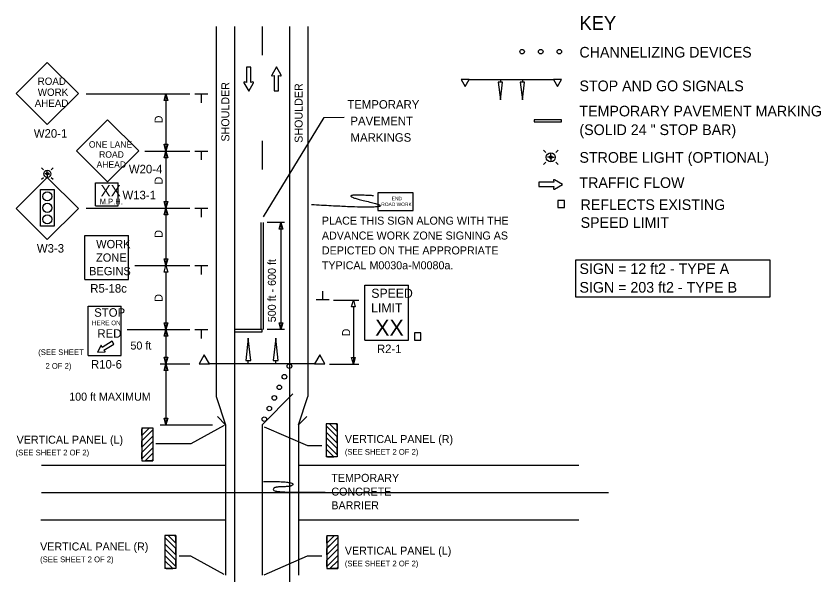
# Model space of a CAD drawing. Extents: x 16739 to 18486, y 7218 to 8208.
# Drawn here: x 16739 to 17443, y 7706 to 8195 of the extents above; entities that cross this region are included whole.
import ezdxf

# ---------------------------------------------------------------- set-up
doc = ezdxf.new("R2010")
doc.units = 0
for name, color, linetype in [('ALI_LEGAL_EX', 7, 'Continuous'), ('MT_SCRATCH_LEVEL_E', 7, 'Continuous'), ('PAVT_EDGE_EX', 7, 'Continuous'), ('TRAFFIC_SIGNS_PR', 7, 'Continuous'), ('TYPICAL_TEXT_DIMEN_EX', 7, 'Continuous'), ('TYPICAL_TEXT_DIMEN_PR', 7, 'Continuous')]:
    doc.layers.add(name, color=color, linetype=linetype)

msp = doc.modelspace()

# ---------------------------------------------------------------- linework, layer by layer
at = {"layer": 'ALI_LEGAL_EX'}
for points in [[(16953.78, 8185.68), (16953.78, 8160.68)], [(16953.78, 8085.68), (16953.78, 8060.68)], [(16952.78, 8014.45), (16952.78, 7920.82)], [(16954.78, 8014.45), (16954.78, 7920.82)]]:
    msp.add_lwpolyline(points, dxfattribs=at)
at = {"layer": 'MT_SCRATCH_LEVEL_E'}
for p, q in [((16943.98, 8150.09), (16940.24, 8150.09)), ((16940.24, 8150.09), (16940.24, 8136.83)), ((16943.98, 8150.09), (16940.24, 8150.09)), ((16940.24, 8150.09), (16940.24, 8136.83)), ((16943.98, 8136.83), (16943.98, 8150.09)), ((16943.98, 8136.83), (16943.98, 8150.09)), ((16966.37, 8150.35), (16962.26, 8143.11)), ((16966.37, 8150.35), (16962.26, 8143.11)), ((16970.52, 8143.11), (16966.37, 8150.35)), ((16970.52, 8143.11), (16966.37, 8150.35)), ((16962.74, 8142.43), (16964.52, 8142.74)), ((16962.74, 8142.43), (16964.52, 8142.74)), ((16964.52, 8142.74), (16964.52, 8129.49)), ((16964.52, 8142.74), (16964.52, 8129.49)), ((16968.26, 8129.49), (16968.26, 8142.74)), ((16968.26, 8142.74), (16970.04, 8142.43)), ((16968.26, 8129.49), (16968.26, 8142.74)), ((16968.26, 8142.74), (16970.04, 8142.43)), ((16937.98, 8136.47), (16942.13, 8129.22)), ((16937.98, 8136.47), (16942.13, 8129.22)), ((16940.24, 8136.83), (16938.46, 8137.15)), ((16940.24, 8136.83), (16938.46, 8137.15)), ((16942.13, 8129.22), (16946.24, 8136.47)), ((16942.13, 8129.22), (16946.24, 8136.47)), ((16945.76, 8137.15), (16943.98, 8136.83)), ((16945.76, 8137.15), (16943.98, 8136.83)), ((16964.52, 8129.49), (16968.26, 8129.49)), ((16964.52, 8129.49), (16968.26, 8129.49)), ((17209.15, 8049.47), (17195.89, 8049.47)), ((17195.89, 8049.47), (17195.89, 8045.73)), ((17209.15, 8049.47), (17195.89, 8049.47)), ((17195.89, 8049.47), (17195.89, 8045.73)), ((17208.83, 8051.25), (17209.15, 8049.47)), ((17208.83, 8051.25), (17209.15, 8049.47)), ((17216.75, 8047.62), (17209.51, 8051.73)), ((17216.75, 8047.62), (17209.51, 8051.73)), ((17209.51, 8043.48), (17216.75, 8047.62)), ((17209.51, 8043.48), (17216.75, 8047.62)), ((17195.89, 8045.73), (17209.15, 8045.73)), ((17195.89, 8045.73), (17209.15, 8045.73)), ((17209.15, 8045.73), (17208.83, 8043.95)), ((17209.15, 8045.73), (17208.83, 8043.95))]:
    msp.add_line(p, q, dxfattribs=at)
for centre, start, end in [((16962.67, 8142.89), 150.42484, 279.96381), ((16962.67, 8142.89), 150.42484, 279.96381), ((16970.11, 8142.89), 260.03619, 29.77312), ((16970.11, 8142.89), 260.03619, 29.77312), ((16938.39, 8136.69), 80.03619, 209.77312), ((16938.39, 8136.69), 80.03619, 209.77312), ((16945.83, 8136.69), 330.42484, 99.96381), ((16945.83, 8136.69), 330.42484, 99.96381), ((17209.29, 8051.33), 60.42484, 189.96381), ((17209.29, 8051.33), 60.42484, 189.96381), ((17209.29, 8043.88), 170.03619, 299.77312), ((17209.29, 8043.88), 170.03619, 299.77312)]:
    msp.add_arc(centre, 0.463, start, end, dxfattribs=at)
at = {"layer": 'PAVT_EDGE_EX'}
for p, q in [((16913.78, 8185.68), (16913.78, 7862.31)), ((16929.78, 8185.68), (16929.78, 7363.75)), ((16977.78, 8185.68), (16977.78, 7363.75)), ((16993.78, 8185.68), (16993.78, 7862.31)), ((16953.78, 7837.6), (16980.8, 7864.62)), ((16913.78, 7862.31), (16921.78, 7837.6)), ((16985.78, 7837.6), (16993.78, 7862.31)), ((16921.78, 7837.6), (16914.71, 7844.68)), ((16985.78, 7837.6), (16992.85, 7844.68)), ((16921.78, 7837.6), (16921.78, 7706.21)), ((16953.78, 7837.6), (16953.78, 7706.21)), ((16985.78, 7837.6), (16985.78, 7706.21)), ((16760.93, 7802.34), (16921.78, 7802.34)), ((16985.78, 7802.34), (17230.97, 7802.34)), ((16760.93, 7778.34), (17256.97, 7778.34)), ((16760.41, 7754.34), (16921.78, 7754.34)), ((16985.78, 7754.34), (17230.97, 7754.34))]:
    msp.add_line(p, q, dxfattribs=at)
for points in [[(16760.93, 7778.34), (16785.93, 7778.34)], [(16860.93, 7778.34), (16885.93, 7778.34)], [(17060.93, 7778.34), (17085.93, 7778.34)], [(17160.93, 7778.34), (17185.93, 7778.34)]]:
    msp.add_lwpolyline(points, dxfattribs=at)
at = {"layer": 'TRAFFIC_SIGNS_PR'}
for p, q in [((16766, 8154.21), (16738.85, 8127.05)), ((16793.15, 8127.05), (16766, 8154.21)), ((17135.1, 8139.38), (17208.7, 8139.38)), ((17162.3, 8139.38), (17162.3, 8136.97)), ((17181.5, 8139.38), (17181.5, 8136.97)), ((16738.85, 8127.05), (16766, 8099.9)), ((16766, 8099.9), (16793.15, 8127.05)), ((16818.78, 8104.04), (16791.63, 8076.89)), ((16845.93, 8076.89), (16818.78, 8104.04)), ((16791.63, 8076.89), (16818.78, 8049.73)), ((16818.78, 8049.73), (16845.93, 8076.89)), ((17202.13, 8075.61), (17200.09, 8077.65)), ((17210.69, 8075.61), (17212.72, 8077.65)), ((17206.41, 8071.33), (17203.53, 8071.33)), ((17206.41, 8071.33), (17206.41, 8074.21)), ((17206.41, 8071.33), (17206.41, 8067.4)), ((17206.41, 8071.33), (17209.28, 8071.33)), ((16762.58, 8060.35), (16760.95, 8061.98)), ((16769.43, 8060.35), (16771.05, 8061.98)), ((17202.13, 8067.05), (17200.09, 8065.02)), ((17212.72, 8065.02), (17210.69, 8067.05)), ((16766, 8053.77), (16738.85, 8026.62)), ((16762.58, 8053.5), (16760.95, 8051.87)), ((16766, 8056.92), (16763.7, 8056.92)), ((16766, 8056.92), (16766, 8059.23)), ((16766, 8056.92), (16766, 8053.77)), ((16766, 8056.92), (16768.3, 8056.92)), ((16793.15, 8026.62), (16766, 8053.77)), ((16771.05, 8051.87), (16769.43, 8053.5)), ((16808.18, 8048.88), (16828.03, 8048.88)), ((16808.18, 8029.03), (16808.18, 8048.88)), ((16828.03, 8029.03), (16828.03, 8048.88)), ((16738.85, 8026.62), (16766, 7999.47)), ((16766, 7999.47), (16793.15, 8026.62)), ((16808.18, 8029.03), (16828.03, 8029.03)), ((16798.72, 7964.51), (16798.72, 8002.91)), ((16798.72, 8002.91), (16837.12, 8002.91)), ((16837.12, 7964.51), (16837.12, 8002.91)), ((16798.72, 7964.51), (16837.12, 7964.51)), ((17043.66, 7959.64), (17082.06, 7959.64)), ((17043.66, 7911.64), (17043.66, 7959.64)), ((17082.06, 7911.64), (17082.06, 7959.64)), ((16801.79, 7941.3), (16830.59, 7941.3)), ((16801.79, 7898.1), (16801.79, 7941.3)), ((16816.19, 7941.3), (16816.19, 7941.3)), ((16830.59, 7898.1), (16830.59, 7941.3)), ((17043.66, 7911.64), (17082.06, 7911.64)), ((16801.79, 7898.1), (16830.59, 7898.1)), ((16941.78, 7890.82), (16941.78, 7893.84)), ((16965.78, 7890.82), (16965.78, 7893.84)), ((16999.78, 7890.82), (16907.78, 7890.82)), ((17019.53, 7838.39), (17009.93, 7838.39)), ((17009.93, 7838.39), (17009.93, 7809.59)), ((17019.53, 7827.12), (17009.93, 7836.72)), ((17019.53, 7831.64), (17012.78, 7838.39)), ((17019.53, 7837.3), (17018.44, 7838.39)), ((17019.53, 7838.39), (17019.53, 7809.59)), ((16848.65, 7834.79), (16858.25, 7834.79)), ((16848.65, 7834.79), (16848.65, 7805.99)), ((16848.65, 7833.71), (16849.74, 7834.79)), ((16848.65, 7828.05), (16855.4, 7834.79)), ((16848.65, 7823.52), (16858.25, 7833.12)), ((16858.25, 7834.79), (16858.25, 7805.99)), ((17019.53, 7821.46), (17009.93, 7831.06)), ((16848.65, 7817.87), (16858.25, 7827.47)), ((16848.65, 7813.34), (16858.25, 7822.94)), ((16850.07, 7824.94), (16851.48, 7826.35)), ((17019.53, 7816.93), (17009.93, 7826.53)), ((16848.65, 7807.68), (16858.25, 7817.28)), ((17019.53, 7811.28), (17009.93, 7820.88)), ((17016.7, 7809.59), (17009.93, 7816.35)), ((16851.49, 7805.99), (16858.25, 7812.76)), ((16857.15, 7805.99), (16858.25, 7807.1)), ((17011.04, 7809.59), (17009.93, 7810.69)), ((17019.53, 7809.59), (17009.93, 7809.59)), ((16848.65, 7805.99), (16858.25, 7805.99)), ((16878.5, 7740.81), (16868.9, 7740.81)), ((16868.9, 7740.81), (16868.9, 7712.01)), ((16878.5, 7729.54), (16868.9, 7739.14)), ((16878.5, 7734.06), (16871.76, 7740.81)), ((16878.5, 7739.72), (16877.41, 7740.81)), ((16878.5, 7740.81), (16878.5, 7712.01)), ((17010.4, 7740.81), (17020, 7740.81)), ((17010.4, 7740.81), (17010.4, 7712.01)), ((17010.4, 7739.72), (17011.49, 7740.81)), ((17010.4, 7734.06), (17017.15, 7740.81)), ((17010.4, 7729.54), (17020, 7739.14)), ((17020, 7740.81), (17020, 7712.01)), ((16878.5, 7723.88), (16868.9, 7733.48)), ((17010.4, 7723.88), (17020, 7733.48)), ((17011.81, 7730.95), (17013.23, 7732.36)), ((16878.5, 7719.35), (16868.9, 7728.95)), ((16878.5, 7713.7), (16868.9, 7723.3)), ((17010.4, 7719.35), (17020, 7728.95)), ((17010.4, 7713.7), (17020, 7723.3)), ((16875.67, 7712.01), (16868.9, 7718.77)), ((17013.24, 7712.01), (17020, 7718.77)), ((16870.01, 7712.01), (16868.9, 7713.11)), ((16878.5, 7712.01), (16868.9, 7712.01)), ((17010.4, 7712.01), (17020, 7712.01)), ((17018.89, 7712.01), (17020, 7713.11))]:
    msp.add_line(p, q, dxfattribs=at)
for points in [[(17127.9, 8139.38), (17131.5, 8133.15), (17135.1, 8139.38)], [(17208.7, 8139.38), (17212.3, 8133.15), (17215.9, 8139.38)], [(17160.5, 8136.97), (17162.3, 8121.43), (17164.1, 8136.97)], [(17179.7, 8136.97), (17181.5, 8121.43), (17183.3, 8136.97)], [(17191.9, 8104.19), (17191.9, 8102.19), (17215.9, 8102.19), (17215.9, 8104.19)], [(16772.06, 8011.17), (16760.06, 8011.17), (16760.06, 8043.17), (16772.06, 8043.17)], [(17055.24, 8024.86), (17085.96, 8024.86), (17085.96, 8040.22), (17055.24, 8040.22)], [(17212.65, 8027.42), (17218.24, 8027.42), (17218.24, 8033.6), (17212.65, 8033.6)], [(16929.78, 7920.82), (16929.78, 7918.82), (16953.78, 7918.82), (16953.78, 7920.82)], [(16944.03, 7893.84), (16941.78, 7913.26), (16939.53, 7893.84)], [(16968.03, 7893.84), (16965.78, 7913.26), (16963.53, 7893.84)], [(17087.07, 7911.64), (17092.67, 7911.64), (17092.67, 7917.81), (17087.07, 7917.81)], [(16907.78, 7890.82), (16903.28, 7898.62), (16898.78, 7890.82)], [(17008.78, 7890.82), (17004.28, 7898.62), (16999.78, 7890.82)], [(17019.53, 7827.12), (17009.93, 7836.72), (17009.93, 7831.06), (17019.53, 7821.46)], [(17018.44, 7838.39), (17012.78, 7838.39), (17019.53, 7831.64), (17019.53, 7837.3)], [(16849.74, 7834.79), (16855.4, 7834.79), (16848.65, 7828.05), (16848.65, 7833.71)], [(16848.65, 7823.52), (16858.25, 7833.12), (16858.25, 7827.47), (16848.65, 7817.87)], [(16848.65, 7813.34), (16858.25, 7822.94), (16858.25, 7817.28), (16848.65, 7807.68)], [(17019.53, 7816.93), (17009.93, 7826.53), (17009.93, 7820.88), (17019.53, 7811.28)], [(17009.93, 7816.35), (17009.93, 7810.69), (17011.04, 7809.59), (17016.7, 7809.59)], [(16858.25, 7812.76), (16858.25, 7807.1), (16857.15, 7805.99), (16851.49, 7805.99)], [(16878.5, 7729.54), (16868.9, 7739.14), (16868.9, 7733.48), (16878.5, 7723.88)], [(16877.41, 7740.81), (16871.76, 7740.81), (16878.5, 7734.06), (16878.5, 7739.72)], [(17011.49, 7740.81), (17017.15, 7740.81), (17010.4, 7734.06), (17010.4, 7739.72)], [(17010.4, 7729.54), (17020, 7739.14), (17020, 7733.48), (17010.4, 7723.88)], [(16878.5, 7719.35), (16868.9, 7728.95), (16868.9, 7723.3), (16878.5, 7713.7)], [(17010.4, 7719.35), (17020, 7728.95), (17020, 7723.3), (17010.4, 7713.7)], [(16868.9, 7718.77), (16868.9, 7713.11), (16870.01, 7712.01), (16875.67, 7712.01)], [(17020, 7718.77), (17020, 7713.11), (17018.89, 7712.01), (17013.24, 7712.01)]]:
    msp.add_lwpolyline(points, close=True, dxfattribs=at)
for points in [[(16812.8, 7906.55), (16809.75, 7900.92), (16816.14, 7901.16)], [(16816.39, 7901.75), (16815.47, 7902.78), (16824.12, 7908.14), (16822.61, 7910.59), (16813.95, 7905.23), (16813.44, 7906.51)]]:
    msp.add_lwpolyline(points, dxfattribs=at)
for centre, radius in [((17181.3, 8163.66), 2), ((17197.6, 8163.66), 2), ((17213.9, 8163.66), 2), ((17206.41, 8071.33), 3.94), ((17206.41, 8071.33), 1.28), ((16766, 8056.92), 3.15), ((16766, 8056.92), 1.02), ((16766.06, 8037.17), 4), ((16766.06, 8027.17), 4), ((16766.06, 8017.17), 4), ((16977.78, 7888.82), 2), ((16973.38, 7879.55), 2), ((16968.98, 7870.29), 2), ((16964.58, 7861.03), 2), ((16960.18, 7851.76), 2), ((16955.78, 7842.5), 2)]:
    msp.add_circle(centre, radius, dxfattribs=at)
for centre, radius, start, end in [((16813.11, 7906.38), 0.355, 21.71521, 151.42661), ((16816.13, 7901.51), 0.354, 272.17868, 41.91782)]:
    msp.add_arc(centre, radius, start, end, dxfattribs=at)
msp.add_open_spline([(17051.39, 8037.68), (17013.6, 8040.07), (17081.62, 8024.59), (16997.05, 8029.86)], degree=2, dxfattribs=at)
at = {"layer": 'TYPICAL_TEXT_DIMEN_EX'}
msp.add_lwpolyline([(17228.42, 7981.57), (17398.08, 7981.57), (17398.08, 7949.02), (17228.42, 7949.02)], close=True, dxfattribs=at)
at = {"layer": 'TYPICAL_TEXT_DIMEN_PR'}
for p, q in [((16799.92, 8126.79), (16890.78, 8126.79)), ((16868.21, 8120.93), (16869.78, 8126.79)), ((16869.78, 8126.79), (16869.78, 8076.79)), ((16869.78, 8126.79), (16871.35, 8120.93)), ((16895.03, 8126.79), (16906.28, 8126.79)), ((16900.66, 8126.79), (16900.66, 8119)), ((16869.78, 8120.93), (16868.21, 8120.93)), ((16871.35, 8120.93), (16869.78, 8120.93)), ((16955.03, 8019.28), (17008.12, 8106.22)), ((17008.12, 8106.22), (17025.74, 8106.43)), ((16869.78, 8076.79), (16868.21, 8082.65)), ((16868.21, 8082.65), (16869.78, 8082.65)), ((16869.78, 8076.79), (16868.21, 8082.65)), ((16868.21, 8082.65), (16869.78, 8082.65)), ((16869.78, 8082.65), (16871.35, 8082.65)), ((16871.35, 8082.65), (16869.78, 8076.79)), ((16869.78, 8082.65), (16871.35, 8082.65)), ((16871.35, 8082.65), (16869.78, 8076.79)), ((16851.17, 8076.79), (16890.78, 8076.79)), ((16868.21, 8070.93), (16869.78, 8076.79)), ((16869.78, 8076.79), (16869.78, 8026.79)), ((16869.78, 8076.79), (16871.35, 8070.93)), ((16895.03, 8076.79), (16906.28, 8076.79)), ((16900.66, 8076.79), (16900.66, 8069)), ((16869.78, 8070.93), (16868.21, 8070.93)), ((16871.35, 8070.93), (16869.78, 8070.93)), ((16869.78, 8026.79), (16868.21, 8032.65)), ((16868.21, 8032.65), (16869.78, 8032.65)), ((16869.78, 8032.65), (16871.35, 8032.65)), ((16871.35, 8032.65), (16869.78, 8026.79)), ((16799.92, 8026.79), (16890.78, 8026.79)), ((16868.21, 8020.93), (16869.78, 8026.79)), ((16869.78, 8026.79), (16871.35, 8020.93)), ((16869.78, 8026.79), (16869.78, 7976.79)), ((16895.03, 8026.79), (16906.28, 8026.79)), ((16900.66, 8026.79), (16900.66, 8019)), ((16869.78, 8020.93), (16868.21, 8020.93)), ((16871.35, 8020.93), (16869.78, 8020.93)), ((16973.59, 8014.45), (16958.31, 8014.45)), ((16968.72, 8008.59), (16970.29, 8014.45)), ((16970.29, 8014.45), (16970.29, 7920.82)), ((16970.29, 8014.45), (16971.86, 8008.59)), ((16970.29, 8008.59), (16968.72, 8008.59)), ((16971.86, 8008.59), (16970.29, 8008.59)), ((16842.46, 7976.79), (16890.78, 7976.79)), ((16869.78, 7976.79), (16868.21, 7982.65)), ((16868.21, 7982.65), (16869.78, 7982.65)), ((16868.21, 7970.93), (16869.78, 7976.79)), ((16869.78, 7982.65), (16871.35, 7982.65)), ((16871.35, 7982.65), (16869.78, 7976.79)), ((16869.78, 7976.79), (16871.35, 7970.93)), ((16895.03, 7976.79), (16906.28, 7976.79)), ((16900.66, 7976.79), (16900.66, 7969)), ((16869.78, 7970.93), (16868.21, 7970.93)), ((16871.35, 7970.93), (16869.78, 7970.93)), ((16869.78, 7970.82), (16869.78, 7920.82)), ((17006.91, 7946.63), (17006.91, 7954.42)), ((17012.53, 7946.63), (17001.28, 7946.63)), ((17016.27, 7946.56), (17038.58, 7946.56)), ((17032.21, 7940.7), (17033.78, 7946.56)), ((17033.78, 7946.56), (17035.35, 7940.7)), ((17033.78, 7940.7), (17032.21, 7940.7)), ((17035.35, 7940.7), (17033.78, 7940.7)), ((17033.78, 7940.6), (17033.78, 7890.6)), ((16835.8, 7920.82), (16890.78, 7920.82)), ((16869.78, 7920.82), (16868.21, 7926.68)), ((16868.21, 7926.68), (16869.78, 7926.68)), ((16868.21, 7914.96), (16869.78, 7920.82)), ((16869.78, 7926.68), (16871.35, 7926.68)), ((16871.35, 7926.68), (16869.78, 7920.82)), ((16869.78, 7920.82), (16869.78, 7890.82)), ((16869.78, 7920.82), (16871.35, 7914.96)), ((16895.03, 7920.82), (16906.28, 7920.82)), ((16900.66, 7920.82), (16900.66, 7913.04)), ((16973.59, 7920.82), (16958.31, 7920.82)), ((16970.29, 7920.82), (16968.72, 7926.68)), ((16968.72, 7926.68), (16970.29, 7926.68)), ((16970.29, 7926.68), (16971.86, 7926.68)), ((16971.86, 7926.68), (16970.29, 7920.82)), ((16869.78, 7914.96), (16868.21, 7914.96)), ((16871.35, 7914.96), (16869.78, 7914.96)), ((16869.78, 7890.82), (16868.21, 7896.68)), ((16868.21, 7896.68), (16869.78, 7896.68)), ((16869.78, 7896.68), (16871.35, 7896.68)), ((16871.35, 7896.68), (16869.78, 7890.82)), ((17033.78, 7890.6), (17032.21, 7896.46)), ((17032.21, 7896.46), (17033.78, 7896.46)), ((17033.78, 7896.46), (17035.35, 7896.46)), ((17035.35, 7896.46), (17033.78, 7890.6)), ((16864.78, 7890.82), (16890.78, 7890.82)), ((16868.21, 7884.96), (16869.78, 7890.82)), ((16869.78, 7884.96), (16868.21, 7884.96)), ((16869.78, 7890.82), (16871.35, 7884.96)), ((16869.78, 7890.82), (16869.78, 7837.6)), ((16871.35, 7884.96), (16869.78, 7884.96)), ((17012.95, 7890.6), (17038.58, 7890.6)), ((16869.78, 7837.6), (16868.21, 7843.47)), ((16868.21, 7843.47), (16869.78, 7843.47)), ((16869.78, 7843.47), (16871.35, 7843.47)), ((16871.35, 7843.47), (16869.78, 7837.6)), ((16864.78, 7837.6), (16910.48, 7837.6)), ((16920.82, 7837.05), (16891.56, 7820.82)), ((16955.78, 7835.85), (16993.57, 7819.41)), ((16891.56, 7820.82), (16860.98, 7820.82)), ((16993.57, 7819.41), (17006.03, 7819.41)), ((16891.56, 7722.81), (16881.31, 7722.81)), ((16920.82, 7706.58), (16891.56, 7722.81)), ((16955.78, 7706.5), (16993.57, 7722.95)), ((16993.57, 7722.95), (17006.03, 7722.95))]:
    msp.add_line(p, q, dxfattribs=at)
msp.add_open_spline([(16955.22, 7788.11), (16980.8, 7788.11), (16980.8, 7783.4), (16963.59, 7783.4), (16963.59, 7778.69), (16996.58, 7778.69), (17009.05, 7778.69)], degree=2, dxfattribs=at)

# ---------------------------------------------------------------- texts
at = {"layer": 'TRAFFIC_SIGNS_PR'}
for s, height, p in [('ROAD', 6.4, (16757.54, 8134.59)), ('WORK', 6.4, (16757.65, 8124.99)), ('AHEAD', 6.4, (16754.96, 8115.39)), ('W20-1', 7.44, (16754.17, 8088.46)), ('ONE LANE', 5.6, (16802.36, 8079.76)), ('ROAD', 5.6, (16811.31, 8070.96)), ('AHEAD', 5.6, (16809.07, 8062.16)), ('W20-4', 7.44, (16837.31, 8057.32)), ('XX', 9.925, (16812.58, 8037.1)), ('W13-1', 7.44, (16831.74, 8034.58)), ('M.P.H.', 4.961, (16811.8, 8030.14)), ('END', 3.065, (17067.24, 8033.76)), ('ROAD WORK', 3.065, (17058.13, 8028.65)), ('PLACE THIS SIGN ALONG WITH THE', 7, (17006.17, 8012.44)), ('ADVANCE WORK ZONE SIGNING AS', 7, (17006.17, 7999.44)), ('WORK', 7.217, (16808.72, 7991.88)), ('W3-3', 7.44, (16756.87, 7988.03)), ('DEPICTED ON THE APPROPRIATE', 7, (17006.17, 7986.44)), ('ZONE', 7.217, (16808.6, 7980.07)), ('TYPICAL M0030a-M0080a.', 7, (17006.17, 7973.44)), ('BEGINS', 7.217, (16802.53, 7968.26)), ('R5-18c', 7.44, (16803.53, 7953.07)), ('SPEED', 8, (17049.42, 7948.5)), ('LIMIT', 8, (17049.26, 7935.7)), ('STOP', 7.44, (16806.99, 7931.96)), ('HERE ON', 4, (16804.99, 7924.6)), ('XX', 14.031, (17052.77, 7915.4)), ('RED', 7.44, (16809.8, 7913.65)), ('R2-1', 7.44, (17054.33, 7900.2)), ('R10-6', 7.44, (16804.17, 7886.66))]:
    msp.add_text(s, height=height, dxfattribs=at).set_placement(p)
at = {"layer": 'TYPICAL_TEXT_DIMEN_EX'}
for s, height, p in [('KEY', 12, (17231.45, 8182.71)), ('CHANNELIZING DEVICES', 9.3, (17231.45, 8158.5)), ('STOP AND GO SIGNALS', 9.3, (17231.45, 8129.1)), ('TEMPORARY PAVEMENT MARKING', 9.3, (17231.45, 8107.05)), ('(SOLID 24 " STOP BAR)', 9.3, (17231.45, 8090.75)), ('STROBE LIGHT (OPTIONAL)', 9.3, (17231.45, 8066.55)), ('TRAFFIC FLOW', 9.3, (17231.45, 8044.5)), ('REFLECTS EXISTING', 9.3, (17232.48, 8025.25)), ('SPEED LIMIT', 9.3, (17232.48, 8009.65)), ('SIGN = 12 ft2 - TYPE A', 9.3, (17231.45, 7969.34)), ('SIGN = 203 ft2 - TYPE B', 9.3, (17231.45, 7953.04))]:
    msp.add_text(s, height=height, dxfattribs=at).set_placement(p)
at = {"layer": 'TYPICAL_TEXT_DIMEN_PR'}
for s, p in [('SHOULDER', (16925.2, 8085.06)), ('SHOULDER', (16989.31, 8083.98)), ('D', (16866.85, 8101.01)), ('D', (16866.85, 8047.59)), ('D', (16866.85, 8001.01)), ('500 ft - 600 ft', (16965.89, 7927.19)), ('D', (16866.85, 7945.04)), ('D', (17030.85, 7914.81))]:
    msp.add_text(s, height=7, rotation=90, dxfattribs=at).set_placement(p)
for s, height, p in [('TEMPORARY', 7.44, (17028.39, 8113.81)), ('PAVEMENT', 7.44, (17031.13, 8099.37)), ('MARKINGS', 7.44, (17031.24, 8084.93)), ('50 ft', 7, (16838.71, 7903.29)), ('(SEE SHEET', 5, (16758.05, 7898.49)), ('2 OF 2)', 5, (16764.38, 7886.49)), ('100 ft MAXIMUM', 7, (16785.14, 7858.6)), ('VERTICAL PANEL (L)', 7, (16739.16, 7821.03)), ('VERTICAL PANEL (R)', 7, (17026.27, 7821.59)), ('(SEE SHEET 2 OF 2)', 5, (16738.27, 7810.78)), ('(SEE SHEET 2 OF 2)', 5, (17026.27, 7811.34)), ('TEMPORARY', 7, (17014.45, 7787.65)), ('CONCRETE', 7, (17014.45, 7775.65)), ('BARRIER', 7, (17014.45, 7763.65)), ('VERTICAL PANEL (R)', 7, (16759.71, 7727.68)), ('VERTICAL PANEL (L)', 7, (17026.25, 7724.04)), ('(SEE SHEET 2 OF 2)', 5, (16759.71, 7717.43)), ('(SEE SHEET 2 OF 2)', 5, (17026.25, 7713.79))]:
    msp.add_text(s, height=height, dxfattribs=at).set_placement(p)

doc.saveas('drawing.dxf')
